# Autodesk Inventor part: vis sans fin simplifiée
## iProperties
Created: 2011-07
Part Number: vis sans fin simplifiée
Document SubType Name: Modeling
Designer: Laur
Density: 7.85 g/cm^3
Material: Acier allié
Mass: 1.75606 g
Surface Area: 3.03993 cm^2
Volume: 0.223702 cm^3
Author: Laur
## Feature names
1. formes arbre [Revolution]
2. cylindre primitif vis [Extrusion]
